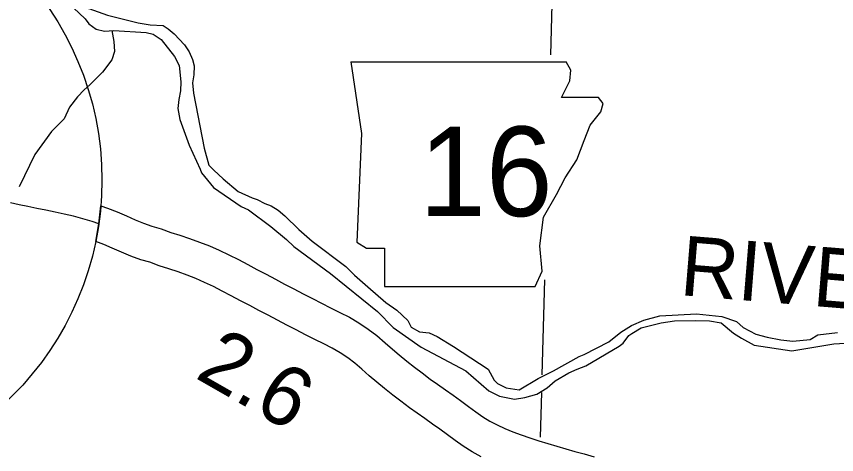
# Model space of a CAD drawing. Extents: x 0 to 3171, y 0 to 2059.
# Drawn here: x 1206.3 to 1303, y 522.5 to 574.1 of the extents above; entities that cross this region are included whole.
import ezdxf

# ---------------------------------------------------------------- set-up
doc = ezdxf.new("R2010")
doc.units = 0
for name, color, linetype in [('Level 10', 7, 'Continuous'), ('Level 21', 7, 'Continuous'), ('Level 35', 7, 'Continuous'), ('Level 48', 7, 'Continuous'), ('Level 5', 7, 'Continuous'), ('Level 63', 7, 'Continuous')]:
    doc.layers.add(name, color=color, linetype=linetype)

msp = doc.modelspace()

# ---------------------------------------------------------------- linework, layer by layer
at = {"layer": 'Level 10'}
for points in [[(1216.055, 549.693), (1215.279, 549.962), (1214.187, 550.282), (1213.089, 550.559), (1211.992, 550.809), (1210.899, 551.043), (1209.817, 551.275), (1208.75, 551.495), (1207.7, 551.712), (1206.662, 551.925), (1205.633, 552.146)], [(1215.692, 547.611), (1216.055, 549.693), (1216.298, 551.814), (1217.09, 551.539), (1218.233, 551.084), (1219.316, 550.613), (1220.336, 550.164), (1221.326, 549.761), (1222.285, 549.411), (1223.392, 549.104), (1224.538, 548.659), (1225.596, 548.324), (1226.748, 547.947), (1227.922, 547.531), (1229.096, 547.068), (1230.25, 546.566), (1231.395, 546.024), (1232.511, 545.452), (1233.601, 544.878), (1234.688, 544.303), (1235.776, 543.73), (1236.868, 543.155), (1237.953, 542.58), (1239.037, 542.008), (1240.125, 541.435), (1241.218, 540.875), (1242.304, 540.317), (1243.368, 539.779), (1244.458, 539.244), (1245.586, 538.657), (1246.712, 537.997), (1247.788, 537.277), (1248.833, 536.496), (1249.782, 535.666), (1250.645, 534.908), (1251.463, 534.219), (1252.349, 533.501), (1253.24, 532.778), (1254.153, 532.099), (1255.094, 531.383), (1255.96, 530.797), (1256.9, 530.129), (1257.8, 529.471), (1258.68, 528.862), (1259.613, 528.153), (1260.467, 527.535), (1261.308, 526.934), (1262.118, 526.426), (1262.977, 525.969), (1263.885, 525.55), (1264.838, 525.166), (1265.826, 524.802), (1266.855, 524.463), (1267.918, 524.118), (1268.972, 523.784), (1270.02, 523.461), (1271.069, 523.157), (1272.145, 522.862), (1273.259, 522.558), (1274.412, 522.229)], [(1261.125, 522.235), (1260.031, 522.816), (1258.986, 523.471), (1258.033, 524.154), (1257.132, 524.806), (1256.233, 525.488), (1255.384, 526.076), (1254.464, 526.748), (1253.585, 527.373), (1252.662, 527.997), (1251.647, 528.77), (1250.683, 529.487), (1249.725, 530.265), (1248.808, 531.007), (1247.927, 531.75), (1247.036, 532.533), (1246.211, 533.254), (1245.381, 533.874), (1244.498, 534.465), (1243.57, 535.009), (1242.578, 535.526), (1241.511, 536.049), (1240.412, 536.604), (1239.316, 537.168), (1238.203, 537.738), (1237.094, 538.322), (1236.006, 538.896), (1234.921, 539.471), (1233.835, 540.043), (1232.743, 540.618), (1231.656, 541.193), (1230.589, 541.755), (1229.553, 542.286), (1228.528, 542.771), (1227.498, 543.219), (1226.461, 543.629), (1225.404, 544.003), (1224.319, 544.358), (1223.154, 544.727), (1222.078, 545.145), (1221.013, 545.44), (1219.827, 545.873), (1218.711, 546.327), (1217.646, 546.796), (1216.631, 547.237), (1215.692, 547.611)]]:
    msp.add_lwpolyline(points, dxfattribs=at)
at = {"layer": 'Level 21'}
for p, q in [((1245.751, 568.783), (1247.02, 560.324)), ((1271.692, 567.796), (1271.107, 568.771)), ((1271.551, 566.528), (1271.692, 567.796)), ((1270.564, 564.554), (1271.551, 566.528)), ((1274.935, 564.554), (1270.564, 564.554)), ((1275.499, 563.849), (1274.935, 564.554)), ((1275.217, 562.862), (1275.499, 563.849)), ((1273.948, 561.311), (1275.217, 562.862)), ((1273.243, 559.478), (1273.948, 561.311)), ((1247.02, 560.324), (1246.456, 547.495)), ((1272.397, 557.223), (1273.243, 559.478)), ((1270.987, 555.108), (1272.397, 557.223)), ((1270, 553.134), (1270.987, 555.108)), ((1268.449, 550.456), (1270, 553.134)), ((1268.027, 547.072), (1268.449, 550.456)), ((1246.456, 547.495), (1247.584, 546.79)), ((1268.308, 544.111), (1268.027, 547.072)), ((1247.584, 546.79), (1249.699, 546.79)), ((1249.699, 546.79), (1249.699, 542.279)), ((1267.463, 542.279), (1268.308, 544.111)), ((1249.699, 542.279), (1267.463, 542.279))]:
    msp.add_line(p, q, dxfattribs=at)
msp.add_lwpolyline([(1245.751, 568.783), (1271.107, 568.771)], dxfattribs=at)
at = {"layer": 'Level 35'}
for points in [[(1208.508, 582.019), (1209.734, 581.021), (1210.937, 579.879), (1212.73, 577.591), (1213.661, 576.25), (1214.171, 575.634), (1214.872, 575.056), (1217.086, 574.271), (1220.696, 573.347), (1222.126, 573.107), (1223.637, 573.034), (1224.238, 572.655), (1224.922, 572.06), (1226.144, 570.751), (1226.697, 569.938), (1227.102, 569.058)], [(1207.01, 580.398), (1210.421, 577.675), (1214.432, 573.836), (1214.884, 573.255), (1215.736, 572.611), (1216.734, 572.385), (1217.829, 572.443), (1221.617, 572.236), (1222.448, 572.042), (1223.416, 571.415), (1224.957, 569.409), (1225.512, 568.33), (1225.725, 566.397), (1225.665, 565.363), (1225.473, 564.328)], [(1217.58, 572.456), (1217.843, 571.164), (1217.89, 569.97), (1217.586, 569.011), (1216.51, 567.536), (1214.989, 566.061), (1214.334, 565.476), (1213.539, 564.634), (1212.603, 563.44), (1211.972, 562.059), (1210.498, 560.538), (1208.533, 557.855), (1206.669, 554.051)], [(1227.102, 569.058), (1227.306, 568.276), (1227.263, 567.225), (1227.087, 566.274), (1227.228, 565.091), (1228.484, 558.598), (1229.03, 556.569), (1229.624, 556.004)], [(1225.473, 564.328), (1225.364, 563.277), (1225.622, 561.979), (1226.689, 558.952), (1228.003, 556.128), (1228.174, 555.671)], [(1229.624, 556.004), (1230.696, 554.976), (1232.483, 553.501), (1234.135, 552.741), (1234.733, 552.53), (1235.599, 552.086), (1236.382, 551.791), (1237.182, 551.28), (1237.967, 550.619), (1239.622, 548.997), (1241.209, 547.625), (1245.181, 544.652), (1246.185, 543.626), (1247.772, 542.237), (1249.893, 540.418), (1251.178, 539.493), (1252.448, 538.302), (1252.869, 537.505), (1253.852, 536.962), (1254.999, 536.836), (1255.915, 536.393), (1257.849, 535.206), (1261.952, 532.551), (1262.625, 531.256), (1263.043, 530.859), (1264.043, 530.332), (1265.572, 530.11), (1267.838, 531.459), (1269.642, 532.356), (1272.67, 534.028), (1273.239, 534.288)], [(1228.174, 555.671), (1229.58, 553.948), (1232.84, 551.713), (1233.695, 551.322), (1236.332, 549.374), (1238.186, 547.82), (1239.038, 546.992), (1243.361, 543.806), (1248.887, 539.344), (1250.743, 537.44), (1254.047, 535.129), (1259.314, 532.333), (1262.02, 529.985), (1263.286, 529.377), (1265.032, 529.022), (1266.259, 529.198), (1267.668, 529.608), (1268.875, 530.367), (1269.816, 531.173), (1271.454, 532.102), (1272.414, 532.542), (1273.449, 532.939)], [(1273.239, 534.288), (1276.153, 535.767), (1277.555, 536.89), (1278.809, 537.689), (1280.26, 538.318), (1282.17, 538.816), (1284.327, 538.932), (1286.477, 539.056), (1289.465, 538.75), (1291.176, 538.169), (1291.984, 537.458), (1293.478, 536.674), (1294.801, 536.331)], [(1273.449, 532.939), (1277.386, 535.255), (1277.847, 535.602), (1278.522, 536.497), (1278.854, 536.768), (1279.962, 537.407), (1282.335, 538.026), (1283.87, 538.224), (1286.328, 538.297), (1288.012, 538.237), (1289.392, 537.991), (1290.833, 536.772), (1291.768, 536.184), (1293.287, 535.375)], [(1294.801, 536.331), (1296.418, 536.012), (1297.814, 535.84), (1299.889, 536.036), (1300.77, 536.576), (1303.098, 536.87)], [(1293.287, 535.375), (1297.721, 534.713), (1302.644, 535.546), (1307.372, 535.816)]]:
    msp.add_lwpolyline(points, dxfattribs=at)
at = {"layer": 'Level 5'}
for points in [[(1269.32, 569.575), (1270.003, 594.951)], [(1268.306, 531.891), (1268.607, 543.091)], [(1268.108, 524.539), (1268.25, 529.814)]]:
    msp.add_lwpolyline(points, dxfattribs=at)
at = {"layer": 'Level 63'}
msp.add_circle((1180.501, 554.832), 35.924, dxfattribs=at)

# ---------------------------------------------------------------- texts
at = {"layer": 'Level 21'}
msp.add_text('16', height=10.56, dxfattribs=at).set_placement((1253.817, 550.581))
at = {"layer": 'Level 35'}
msp.add_text('RIVER', height=7.04, rotation=355.33857, dxfattribs=at).set_placement((1284.395, 541.286))
at = {"layer": 'Level 48'}
msp.add_text('2.6', height=7.04, rotation=330.23823, dxfattribs=at).set_placement((1227.246, 531.606))

doc.saveas('drawing.dxf')
